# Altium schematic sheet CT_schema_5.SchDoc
size 300 x 247 mm
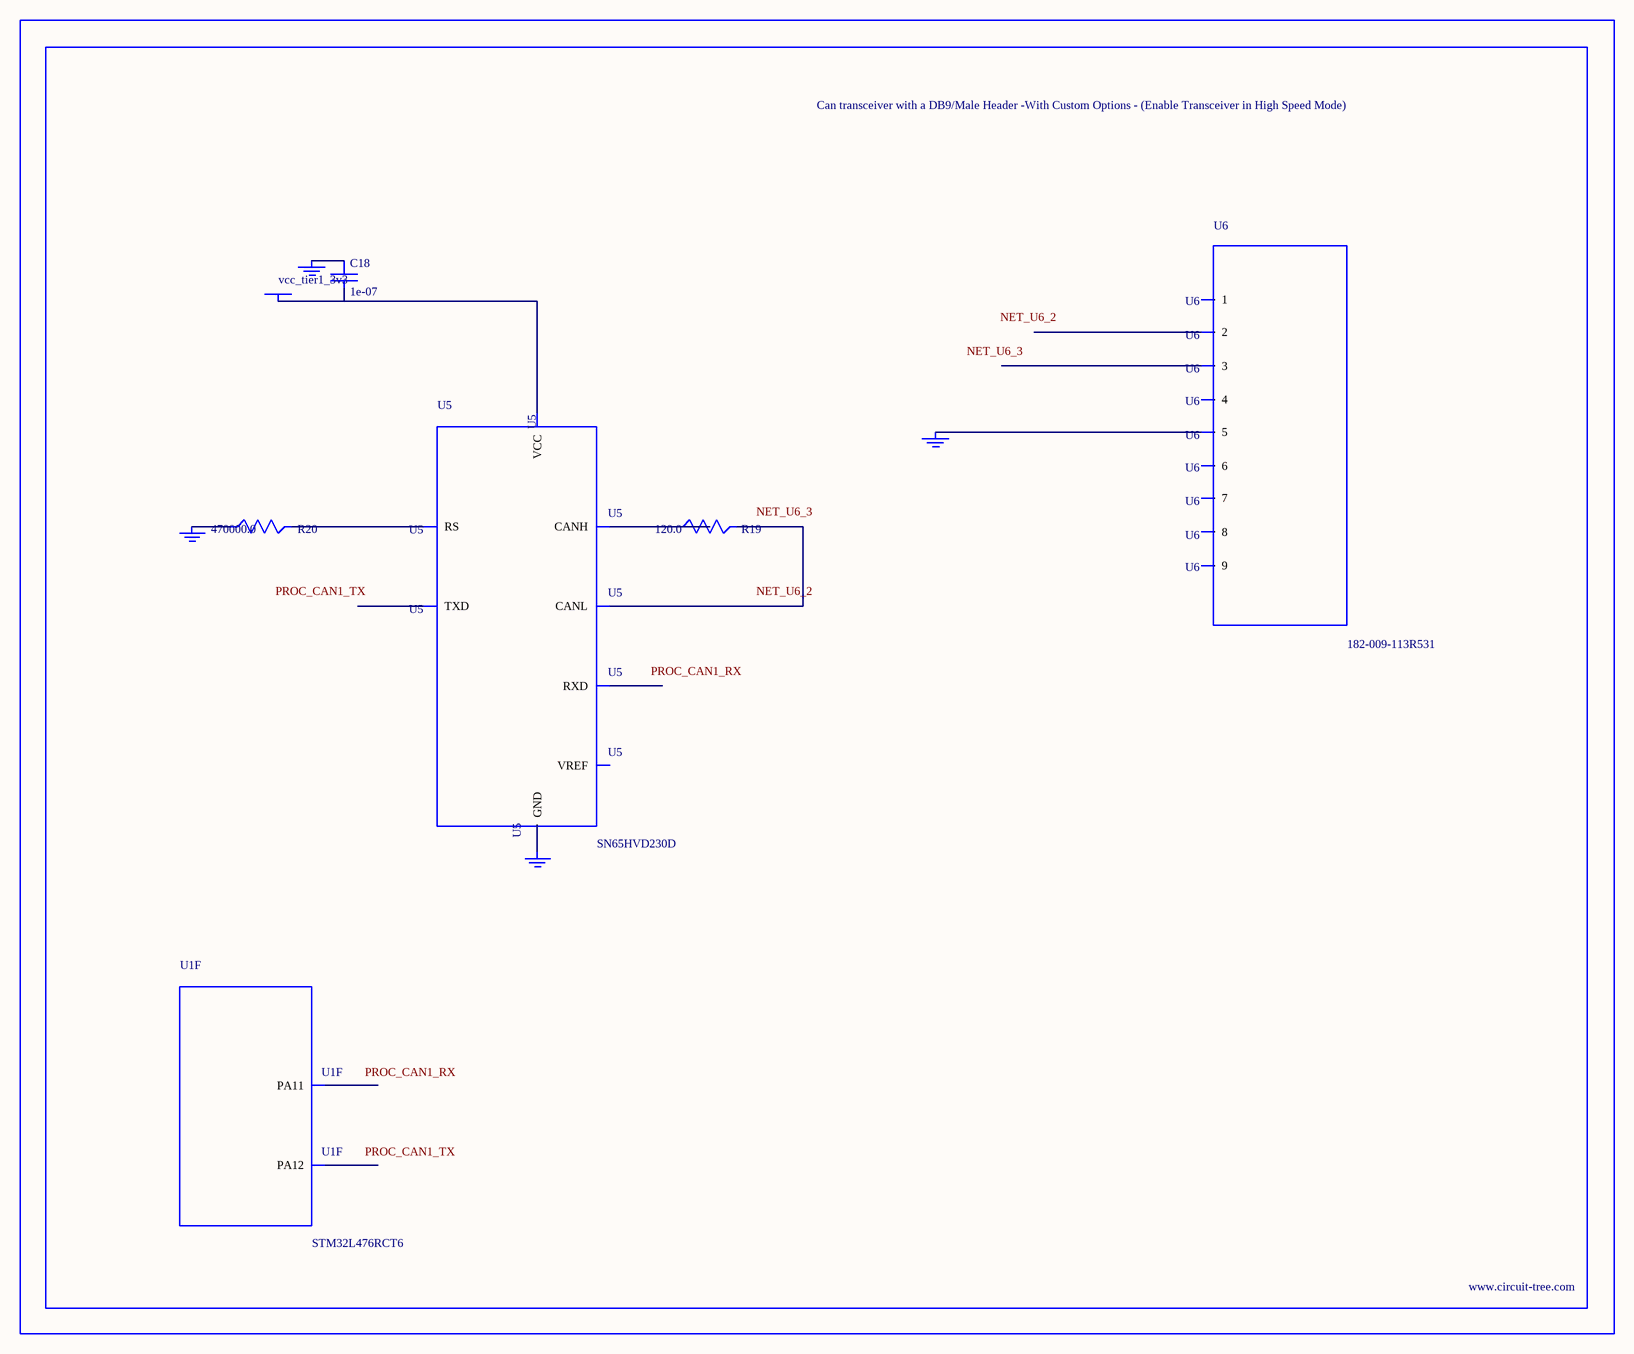
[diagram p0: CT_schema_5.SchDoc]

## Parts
BORDER4  (no value)
C18  1e-07  [C0402]
GND_INSTANCE_4_0  (no value)
GND_INSTANCE_4_1  (no value)
GND_INSTANCE_4_2  (no value)
GND_INSTANCE_4_3  (no value)
POWER_INSTANCE_4_0  vcc_tier1_3v3
R19  120.0  [R0603]
R20  470000.0  [R0603]
U1  STM32L476RCT6  [LQFP64]  (part F of 6)
U5  SN65HVD230D  [SOIC-8]
U6  182-009-113R531  [182-009-MALE]

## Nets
NetC18_1: C18.1 GND_INSTANCE_4_0.0(GND)
NetC18_2: C18.2 POWER_INSTANCE_4_0.0(PWR) U5.3(VCC)
NetGND_INSTANCE_4_1_0: GND_INSTANCE_4_1.0(GND) R20.1
NetGND_INSTANCE_4_2_0: GND_INSTANCE_4_2.0(GND) U5.2(GND)
NetGND_INSTANCE_4_3_0: GND_INSTANCE_4_3.0(GND) U6.5
NetR19_1: R19.1 U5.7(CANH)
NetR19_2: R19.2 U5.6(CANL)
NetR20_2: R20.2 U5.8(RS)

Not connected (* = marked no-connect by the designer): U1 44(PA11) 45(PA12); U5 1(TXD) 4(RXD) 5(VREF); U6 1 2 3 4 6 7 8 9

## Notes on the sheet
- Labels drawn without touching a wire or pin: NET_U6_2, NET_U6_3, PROC_CAN1_RX, PROC_CAN1_TX

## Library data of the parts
BORDER4 = BORDER_PAGE4
C18 = C0402C104K3RACTU
GND_INSTANCE_4_0-GND_INSTANCE_4_3 = GND
POWER_INSTANCE_4_0 = PWR
R19 = RC0603JR-07120RL
R20 = RC0603JR-07470KL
